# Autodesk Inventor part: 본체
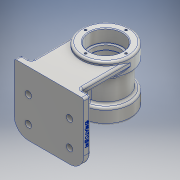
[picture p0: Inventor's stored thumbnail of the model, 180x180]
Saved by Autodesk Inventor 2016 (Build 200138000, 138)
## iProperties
Created: 2020-06
Part Number: 본체
Material: 알루미늄 6061
Document SubType Name: Modeling
Designer: user
Density: 2.7 g/cm^3
Appearance: 알루미늄 - 평지
Mass: 722.614 g
Surface Area: 637.026 cm^2
Volume: 267.635 cm^3
Author: user
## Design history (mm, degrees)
sketch "스케치1"
  geometry: C1 r 29 at (0, 0); 1 further point
  constraints: 1 centre point, 1 coincident
  dimensions: "d0" = 58 diameter of C1
extrude "돌출1" new body sketch "스케치1" stored distance "d1" = 78; taper "d2" = 0 deg
sketch "스케치2"
  geometry: C1 r 35 at (0, 0); 1 further point
  constraints: 1 centre point, 1 coincident
  dimensions: "d3" = 70 diameter of C1
extrude "돌출2" join sketch "스케치2" distance "d4" = 22; taper "d5" = 0 deg
sketch "스케치3"
  geometry: C1 r 35 at (0, 0); 1 further point
  constraints: 1 centre point, 1 coincident
  dimensions: "d6" = 70 diameter of C1
extrude "돌출3" join sketch "스케치3" distance "d7" = 22; taper "d8" = 0 deg
sketch "스케치4"
  geometry: C1 r 6 at (0, 0); 1 further point
  constraints: 1 centre point, 1 coincident
  dimensions: "d9" = 12 diameter of C1
extrude "돌출4" join sketch "스케치4" distance "d10" = 32; taper "d11" = 0 deg
fillet "모깎기1" dims "d12" = 3
sketch "스케치5"
  geometry: L1 (0, 0)-(0, -80); L2 (-49, -80)-(49, -80); L3 (-49, -70)-(49, -70); L4 (49, -70)-(49, -80); L5 (-49, -70)-(-49, -80)
  constraints: 10 end point, 3 vertical, 1 horizontal, 1 midpoint, 1 parallel
  dimensions: "d13" = 80 distance of L1.end L1.start; "d14" = 98 distance of L2.start L2.end; "d15" = 10 distance between parallel lines of L2 L3
extrude "돌출5" join sketch "스케치5" distance "d16" = 95; taper "d17" = 0 deg
sketch "스케치6"
  geometry: L1 (-49, -80)-(-49, -70) reference; L2 (-49, -70)-(49, -70) reference; L3 (-49, -70)-(49, -70); L4 (49, -70)-(49, -80) reference; L5 (49, -70)-(49, -80); L6 (49, -80)-(-49, -80) reference; L7 (49, -80)-(-49, -80); L8 (-49, -80)-(-49, -70); 1 further point
  constraints: 8 end point, 2 perpendicular, 1 collinear, 1 horizontal
extrude "돌출6" cut sketch "스케치6" distance "d18" = 5; taper "d19" = 0 deg
sketch "스케치7"
  geometry: L1 (14, -90)-(84, -90); L2 (0, -90)-(98, -90) reference; L3 (14, -90)-(14, -80); L4 (14, -80)-(84, -80); L5 (84, -80)-(84, -90); 2 further points
  constraints: 8 end point, 2 midpoint, 1 horizontal, 1 perpendicular, 1 vertical
  dimensions: "d20" = 70 distance of L1.start L1.end; "d21" = 10 distance of L1.start L3.end; "d22" = 70 distance of L3.end L4.end
extrude "돌출7" join sketch "스케치7" distance "d23" = 70; taper "d24" = 0 deg
sketch "스케치8"
  geometry: L1 (-70, -44)-(-9.089, -21.83); L2 (-70, -44)-(-70, 26.867); L3 (-70, 26.867)-(9.107, 26.867); L4 (-9.089, -21.83)-(9.107, 26.867); 2 further points
  constraints: 8 end point, 1 horizontal, 1 vertical
  dimensions: "d25" = 12 distance of point (-70, -56) L1.start
extrude "돌출8" join sketch "스케치8" stored distance "d27" = 10; taper "d28" = 0 deg
sketch "스케치9"
  geometry: L1 (78, 90)-(20, 90); L2 (98, 90)-(0, 90) reference; L3 (78, 20)-(20, 20); L4 (78, 56)-(20, 56); C1 r 4.5 at (78, 20); C2 r 4.5 at (78, 56); C3 r 4.5 at (20, 20); C4 r 4.5 at (20, 56); 2 further points
  constraints: 6 end point, 4 centre point, 4 coincident, 2 midpoint, 2 parallel, 1 horizontal
  dimensions: "d29" = 58 distance of L1.start L1.end; "d30" = 70 distance between parallel lines of L1 L3; "d31" = 36 distance between parallel lines of L3 L4; "d32" = 9 diameter of C1; "d33" = 9 diameter of C2; "d34" = 9 diameter of C3; "d35" = 9 diameter of C4
extrude "돌출9" cut sketch "스케치9" distance "d36" = 15; taper "d37" = 0 deg
sketch "스케치10"
  geometry: C1 r 23.5 at (0, 0); 1 further point
  constraints: 1 centre point, 1 coincident
  dimensions: "d38" = 47 diameter of C1
extrude "돌출10" cut sketch "스케치10" distance "d39" = 18; taper "d40" = 0 deg
sketch "스케치11"
  geometry: C1 r 20 at (0, 0); 1 further point
  constraints: 1 centre point, 1 coincident
  dimensions: "d41" = 40 diameter of C1
extrude "돌출11" cut sketch "스케치11" distance "d42" = 6; taper "d43" = 0 deg
sketch "스케치12"
  geometry: C1 r 23 at (0, 0); 1 further point
  constraints: 1 centre point, 1 coincident
  dimensions: "d44" = 46 diameter of C1
extrude "돌출12" cut sketch "스케치12" distance "d45" = 30; taper "d46" = 0 deg
sketch "스케치13"
  geometry: C1 r 20 at (0, 0); 1 further point
  constraints: 1 centre point, 1 coincident
  dimensions: "d47" = 40 diameter of C1
extrude "돌출13" cut sketch "스케치13" distance "d48" = 6; taper "d49" = 0 deg
sketch "스케치14"
  geometry: C1 r 23.5 at (0, 0); 1 further point
  constraints: 1 centre point, 1 coincident
  dimensions: "d50" = 47 diameter of C1
extrude "돌출14" cut sketch "스케치14" distance "d51" = 18; taper "d52" = 0 deg
chamfer "모따기1" distance "d53" = 1; stored, may be unused: second distance "d54" = 2, angle "d55" = 45 deg
fillet "모깎기2" dims "d56" = 3
fillet "모깎기3" dims "d57" = 3
fillet "모깎기4" dims "d58" = 3
fillet "모깎기5" dims "d59" = 3
fillet "모깎기6" dims "d60" = 20
fillet "모깎기7" dims "d61" = 3
sketch "스케치16"
  geometry: L1 (-3, 0)-(42, 0); L2 (-3, 4)-(42, 4); L3 (87, 0)-(67, 0) reference; L4 (-3, 8)-(87, 8); L5 (87, 8)-(87, 0); L6 (87, 0)-(-3, 0); L7 (-3, 0)-(-3, 8); L8 (-3, 8)-(87, 0); L9 (87, 8)-(-3, 0); L10 (-3, 8)-(87, 8); L11 (87, 8)-(87, 0); L12 (87, 0)-(-3, 0); L13 (-3, 0)-(-3, 8); 2 further points
  constraints: 16 end point, 3 coincident, 3 parallel, 2 horizontal, 2 midpoint, 1 perpendicular, 2 other
  dimensions: "d62" = 45 distance of L1.start L1.end; "d63" = 4 distance between parallel lines of L1 L2
feature "엠보싱1" sketch "스케치16" dims "d64" = 0.5, "d65" = 0
sketch "스케치17"
  geometry: A1 r 28.5 centre (0, 0) between (0, 28.5) and (-28.5, 0); 3 further points
  constraints: 4 point on circle, 1 centre point, 1 coincident
  dimensions: "d66" = 57 diameter of A1
hole "구멍1" sketch "스케치17" at (0, 28.5), (-28.5, 0), (0, -28.5), (28.5, 0) diameter "d67" = 3.242; stored, may be unused: countersink angle "d71" = 90 deg, drill point angle "d73" = 118 deg; dims "d68" = 10, "d69" = 4, "d70" = 2, "d72" = 12
sketch "스케치18"
  geometry: C1 r 1.621 at (-28.5, 0) reference; A1 r 28.5 centre (0, 0) between (0, 28.5) and (0, -28.5); 3 further points
  constraints: 3 point on circle, 2 coincident, 1 centre point
  dimensions: "d74" = 57 diameter of A1
hole "구멍2" sketch "스케치18" at (0, 28.5), (-28.5, 0), (0, -28.5), (28.5, 0) diameter "d75" = 3.242; stored, may be unused: countersink angle "d79" = 90 deg, drill point angle "d81" = 118 deg; dims "d76" = 10, "d77" = 4, "d78" = 2, "d80" = 12
sketch "스케치19"
  geometry: 2 further points
  constraints: 1 coincident
hole "구멍3" sketch "스케치19" at (0, 0) diameter "d83" = 5.188; stored, may be unused: countersink angle "d87" = 82 deg, drill point angle "d89" = 118 deg; dims "d84" = 12, "d85" = 3.023, "d86" = 2, "d88" = 16
fillet "모깎기8" dims "d90" = 0.3
fillet "모깎기9" dims "d91" = 3
node "솔리드1"
